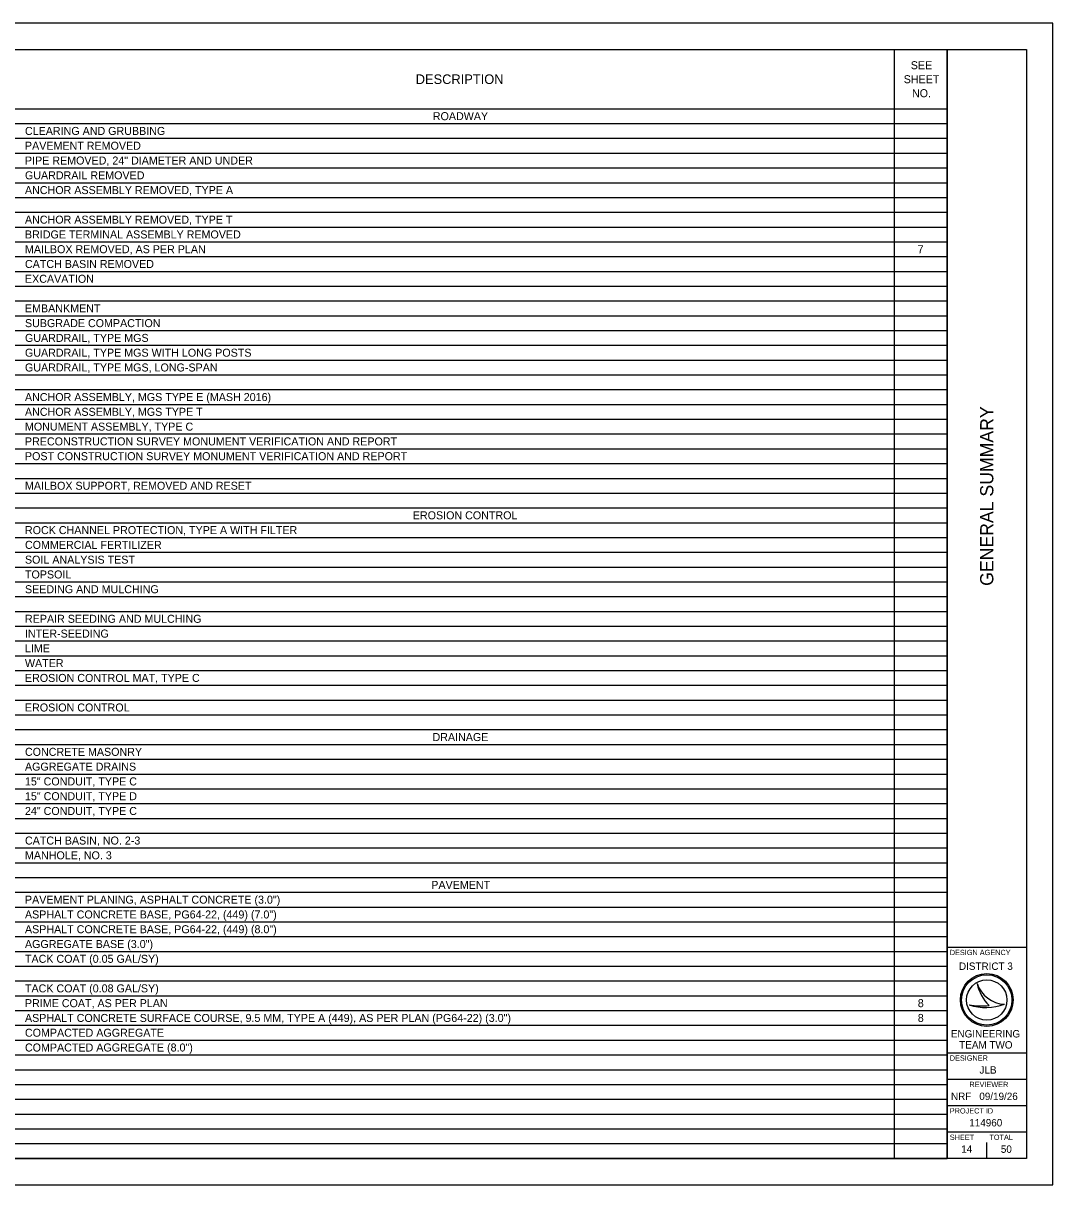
# Model space of a CAD drawing. Extents: x 0 to 34, y 0 to 22.
# Drawn here: x 14.5 to 34, y 0 to 22 of the extents above; entities that cross this region are included whole.
import ezdxf

# ---------------------------------------------------------------- set-up
doc = ezdxf.new("R2010")
doc.units = 0
for name, color, linetype in [('Default', 7, 'Continuous'), ('SH_Border', 7, 'Continuous'), ('SH_Cut_Line', 7, 'Continuous'), ('SH_Data', 7, 'Continuous')]:
    doc.layers.add(name, color=color, linetype=linetype)

msp = doc.modelspace()

# ---------------------------------------------------------------- linework, layer by layer
at = {"layer": 'Default'}
for p, q in [((1.5, 21.5), (32, 21.5)), ((30.996, 21.5), (30.996, 0.5)), ((32, 21.5), (32, 0.5)), ((1.5, 20.38), (32, 20.38)), ((1.5, 20.1), (32, 20.1)), ((1.5, 19.82), (32, 19.82)), ((1.5, 19.54), (32, 19.54)), ((1.5, 19.26), (32, 19.26)), ((1.5, 18.98), (32, 18.98)), ((1.5, 18.7), (32, 18.7)), ((1.5, 18.42), (32, 18.42)), ((1.5, 18.14), (32, 18.14)), ((1.5, 17.86), (32, 17.86)), ((1.5, 17.58), (32, 17.58)), ((1.5, 17.3), (32, 17.3)), ((1.5, 17.02), (32, 17.02)), ((1.5, 16.74), (32, 16.74)), ((1.5, 16.46), (32, 16.46)), ((1.5, 16.18), (32, 16.18)), ((1.5, 15.9), (32, 15.9)), ((1.5, 15.62), (32, 15.62)), ((1.5, 15.34), (32, 15.34)), ((1.5, 15.06), (32, 15.06)), ((1.5, 14.78), (32, 14.78)), ((1.5, 14.5), (32, 14.5)), ((1.5, 14.22), (32, 14.22)), ((1.5, 13.94), (32, 13.94)), ((1.5, 13.66), (32, 13.66)), ((1.5, 13.38), (32, 13.38)), ((1.5, 13.1), (32, 13.1)), ((1.5, 12.82), (32, 12.82)), ((1.5, 12.54), (32, 12.54)), ((1.5, 12.26), (32, 12.26)), ((1.5, 11.98), (32, 11.98)), ((1.5, 11.7), (32, 11.7)), ((1.5, 11.42), (32, 11.42)), ((1.5, 11.14), (32, 11.14)), ((1.5, 10.86), (32, 10.86)), ((1.5, 10.58), (32, 10.58)), ((1.5, 10.3), (32, 10.3)), ((1.5, 10.02), (32, 10.02)), ((1.5, 9.74), (32, 9.74)), ((1.5, 9.46), (32, 9.46)), ((1.5, 9.18), (32, 9.18)), ((1.5, 8.9), (32, 8.9)), ((1.5, 8.62), (32, 8.62)), ((1.5, 8.34), (32, 8.34)), ((1.5, 8.06), (32, 8.06)), ((1.5, 7.78), (32, 7.78)), ((1.5, 7.5), (32, 7.5)), ((1.5, 7.22), (32, 7.22)), ((1.5, 6.94), (32, 6.94)), ((1.5, 6.66), (32, 6.66)), ((1.5, 6.38), (32, 6.38)), ((1.5, 6.1), (32, 6.1)), ((1.5, 5.82), (32, 5.82)), ((1.5, 5.54), (32, 5.54)), ((1.5, 5.26), (32, 5.26)), ((1.5, 4.98), (32, 4.98)), ((1.5, 4.7), (32, 4.7)), ((1.5, 4.42), (32, 4.42)), ((1.5, 4.14), (32, 4.14)), ((1.5, 3.86), (32, 3.86)), ((1.5, 3.58), (32, 3.58)), ((1.5, 3.3), (32, 3.3)), ((1.5, 3.02), (32, 3.02)), ((1.5, 2.74), (32, 2.74)), ((1.5, 2.46), (32, 2.46)), ((1.5, 2.18), (32, 2.18)), ((1.5, 1.9), (32, 1.9)), ((1.5, 1.62), (32, 1.62)), ((1.5, 1.34), (32, 1.34)), ((1.5, 1.06), (32, 1.06)), ((1.5, 0.78), (32, 0.78)), ((1.5, 0.5), (32, 0.5))]:
    msp.add_line(p, q, dxfattribs=at)
at = {"layer": 'SH_Border'}
for p, q in [((32, 0.5), (32, 21.5)), ((32, 4.5), (33.5, 4.5)), ((32, 2.5), (33.5, 2.5)), ((32, 2), (33.5, 2)), ((32, 1.5), (33.5, 1.5)), ((32, 1), (33.5, 1))]:
    msp.add_line(p, q, dxfattribs=at)
msp.add_lwpolyline([(1.5, 21.5), (33.5, 21.5), (33.5, 0.5), (1.5, 0.5)], close=True, dxfattribs=at)
at = {"layer": 'SH_Cut_Line'}
msp.add_lwpolyline([(0, 0), (34, 0), (34, 22), (0, 22)], close=True, dxfattribs=at)
at = {"layer": 'SH_Data'}
for p, q in [((32.567, 3.81), (32.567, 3.81)), ((32.417, 3.41), (32.417, 3.41)), ((32.75, 3.5), (32.75, 3.5)), ((33.087, 3.419), (33.087, 3.419)), ((32.375, 0.675), (32.375, 0.675)), ((32.75, 0.5), (32.75, 0.8))]:
    msp.add_line(p, q, dxfattribs=at)
for radius in [0.5, 0.477, 0.477, 0.382]:
    msp.add_circle((32.75, 3.5), radius, dxfattribs=at)
for centre, radius, start, end in [((33.116, 3.998), 0.58, 198.9257, 198.9319), ((33.347, 3.97), 0.796, 191.6379, 191.6421), ((33.116, 3.998), 0.58, 198.9319, 267.1657), ((33.347, 3.97), 0.796, 191.6421, 226.0947), ((32.739, 4.37), 1.013, 251.4576, 290.0832), ((32.648, 4.654), 1.266, 259.4964, 259.4995), ((32.739, 4.37), 1.013, 251.4527, 251.4576), ((32.648, 4.654), 1.266, 259.4995, 276.6672)]:
    msp.add_arc(centre, radius, start, end, dxfattribs=at)

# ---------------------------------------------------------------- texts
at = {"layer": 'Default'}
for s, height, p in [('SEE ', 0.1515, (31.311, 21.129)), ('DESCRIPTION', 0.18184, (21.937, 20.849)), ('SHEET ', 0.1515, (31.177, 20.864)), ('NO.', 0.1515, (31.334, 20.599)), ('ROADWAY', 0.1515, (22.26, 20.164)), ('CLEARING AND GRUBBING', 0.15153, (14.536, 19.884)), ('PAVEMENT REMOVED', 0.15153, (14.536, 19.604)), ('PIPE REMOVED, 24" DIAMETER AND UNDER', 0.15153, (14.536, 19.324)), ('GUARDRAIL REMOVED', 0.15153, (14.536, 19.044)), ('ANCHOR ASSEMBLY REMOVED, TYPE A', 0.15153, (14.536, 18.764)), ('ANCHOR ASSEMBLY REMOVED, TYPE T', 0.15153, (14.536, 18.204)), ('BRIDGE TERMINAL ASSEMBLY REMOVED', 0.15153, (14.536, 17.924)), ('MAILBOX REMOVED, AS PER PLAN', 0.15153, (14.536, 17.644)), ('7', 0.152, (31.44, 17.644)), ('CATCH BASIN REMOVED', 0.15153, (14.536, 17.364)), ('EXCAVATION', 0.1515, (14.536, 17.084)), ('EMBANKMENT', 0.1515, (14.536, 16.524)), ('SUBGRADE COMPACTION', 0.15153, (14.536, 16.244)), ('GUARDRAIL, TYPE MGS', 0.15153, (14.536, 15.964)), ('GUARDRAIL, TYPE MGS WITH LONG POSTS', 0.15153, (14.536, 15.684)), ('GUARDRAIL, TYPE MGS, LONG-SPAN', 0.15153, (14.536, 15.404)), ('ANCHOR ASSEMBLY, MGS TYPE E (MASH 2016)', 0.15153, (14.536, 14.844)), ('ANCHOR ASSEMBLY, MGS TYPE T', 0.15153, (14.536, 14.564)), ('MONUMENT ASSEMBLY, TYPE C', 0.15153, (14.536, 14.284)), ('PRECONSTRUCTION SURVEY MONUMENT VERIFICATION AND REPORT', 0.15153, (14.536, 14.004)), ('POST CONSTRUCTION SURVEY MONUMENT VERIFICATION AND REPORT', 0.15153, (14.536, 13.724)), ('MAILBOX SUPPORT, REMOVED AND RESET', 0.15153, (14.536, 13.164)), ('EROSION CONTROL', 0.15153, (21.881, 12.604)), ('ROCK CHANNEL PROTECTION, TYPE A WITH FILTER', 0.15153, (14.536, 12.324)), ('COMMERCIAL FERTILIZER', 0.15153, (14.536, 12.044)), ('SOIL ANALYSIS TEST', 0.15153, (14.536, 11.764)), ('TOPSOIL', 0.1515, (14.536, 11.484)), ('SEEDING AND MULCHING', 0.15153, (14.536, 11.204)), ('REPAIR SEEDING AND MULCHING', 0.15153, (14.536, 10.644)), ('INTER-SEEDING', 0.15153, (14.536, 10.364)), ('LIME', 0.1515, (14.536, 10.084)), ('WATER', 0.1515, (14.536, 9.804)), ('EROSION CONTROL MAT, TYPE C', 0.15153, (14.536, 9.524)), ('EROSION CONTROL', 0.15153, (14.536, 8.964)), ('DRAINAGE', 0.1515, (22.254, 8.404)), ('CONCRETE MASONRY', 0.15153, (14.536, 8.124)), ('AGGREGATE DRAINS', 0.15153, (14.536, 7.844)), ('15" CONDUIT, TYPE C', 0.15153, (14.536, 7.564)), ('15" CONDUIT, TYPE D', 0.15153, (14.536, 7.284)), ('24" CONDUIT, TYPE C', 0.15153, (14.536, 7.004)), ('CATCH BASIN, NO. 2-3', 0.15153, (14.536, 6.444)), ('MANHOLE, NO. 3', 0.15153, (14.536, 6.164)), ('PAVEMENT', 0.1515, (22.231, 5.604)), ('PAVEMENT PLANING, ASPHALT CONCRETE (3.0")', 0.15153, (14.536, 5.324)), ('ASPHALT CONCRETE BASE, PG64-22, (449) (7.0")', 0.15153, (14.536, 5.044)), ('ASPHALT CONCRETE BASE, PG64-22, (449) (8.0")', 0.15153, (14.536, 4.764)), ('AGGREGATE BASE (3.0")', 0.15153, (14.536, 4.484)), ('TACK COAT (0.05 GAL/SY)', 0.15153, (14.536, 4.204)), ('TACK COAT (0.08 GAL/SY)', 0.15153, (14.536, 3.644)), ('PRIME COAT, AS PER PLAN', 0.15153, (14.536, 3.364)), ('8', 0.152, (31.444, 3.364)), ('ASPHALT CONCRETE SURFACE COURSE, 9.5 MM, TYPE A (449), AS PER PLAN (PG64-22) (3.0")', 0.15153, (14.536, 3.084)), ('8', 0.152, (31.444, 3.084)), ('COMPACTED AGGREGATE', 0.15153, (14.536, 2.804)), ('COMPACTED AGGREGATE (8.0")', 0.15153, (14.536, 2.524))]:
    msp.add_text(s, height=height, dxfattribs=at).set_placement(p)
at = {"layer": 'SH_Data'}
msp.add_text('GENERAL SUMMARY', height=0.25, rotation=90, dxfattribs=at).set_placement((32.875, 11.344))
for s, height, p in [('DESIGN AGENCY', 0.1, (32.05, 4.35)), ('DISTRICT 3', 0.14, (32.224, 4.07)), ('ENGINEERING', 0.14, (32.071, 2.79)), ('TEAM TWO', 0.14, (32.229, 2.58)), ('DESIGNER', 0.1, (32.05, 2.35)), ('JLB', 0.14, (32.613, 2.105)), ('REVIEWER', 0.1, (32.422, 1.85)), ('NRF', 0.14, (32.073, 1.605)), ('09/19/26', 0.14, (32.609, 1.605)), ('PROJECT ID', 0.1, (32.05, 1.35)), ('114960', 0.14, (32.419, 1.105)), ('SHEET', 0.1, (32.05, 0.85)), ('TOTAL', 0.1, (32.8, 0.85)), ('14', 0.14, (32.266, 0.605)), ('50', 0.14, (33.017, 0.605))]:
    msp.add_text(s, height=height, dxfattribs=at).set_placement(p)

doc.saveas('drawing.dxf')
